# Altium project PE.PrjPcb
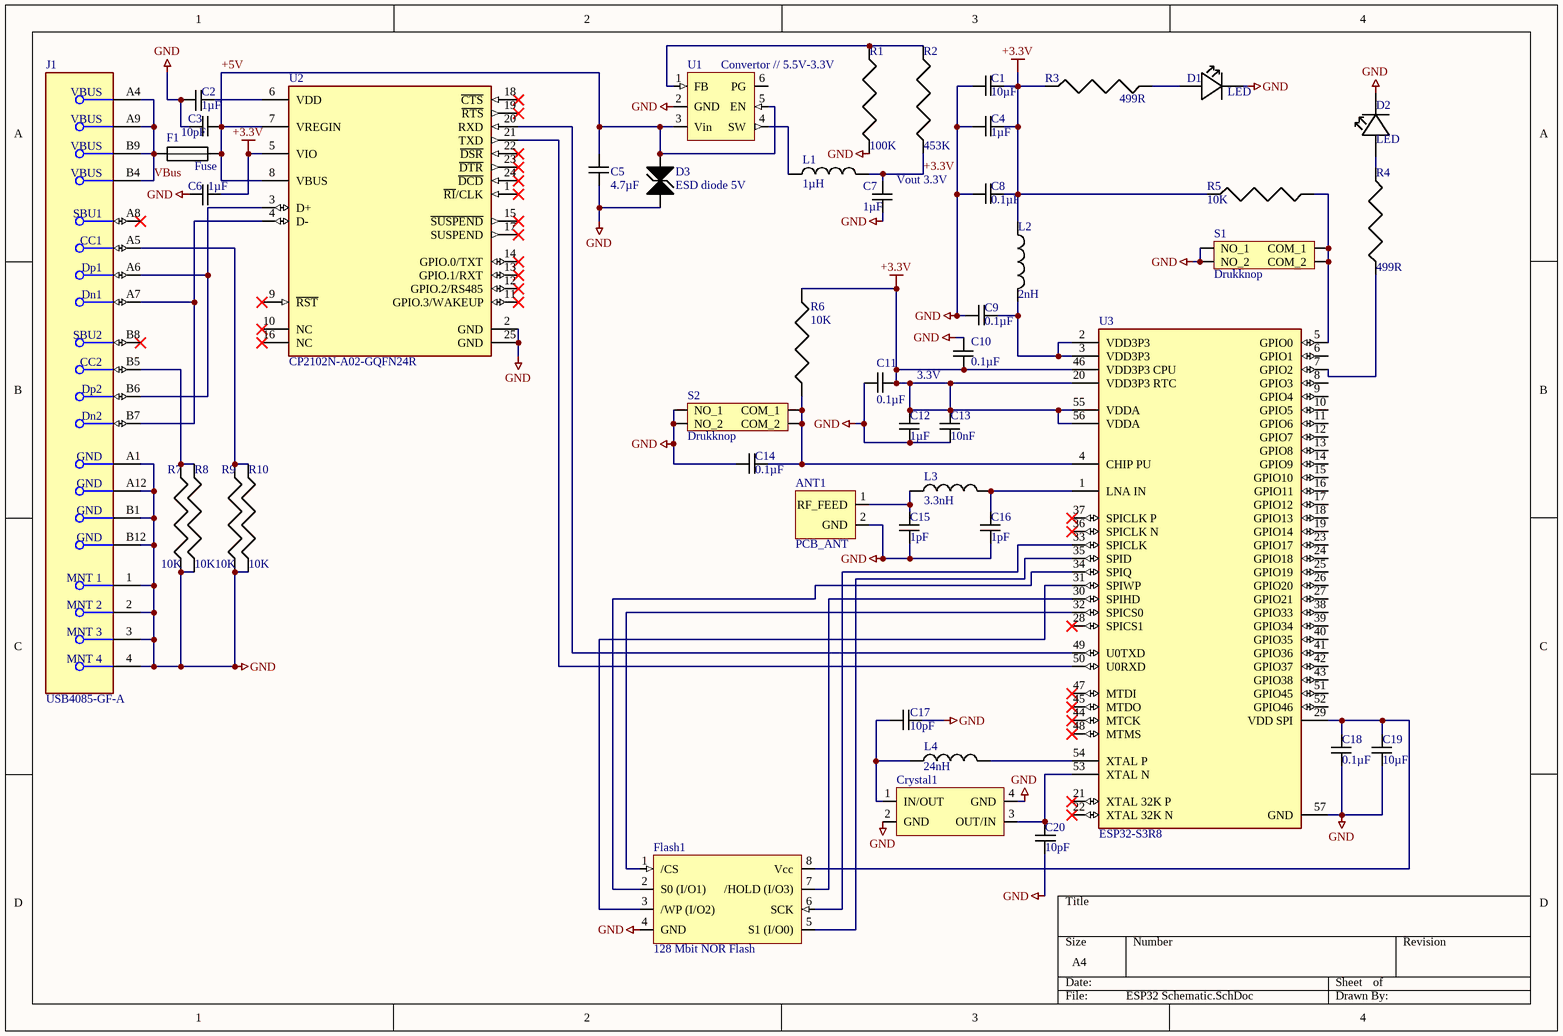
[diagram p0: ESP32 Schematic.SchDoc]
1 sheet, 47 parts. Net scope: global (net labels, ports and power ports of the same name join across sheets).
Board files: PCB-v1.PcbDoc, PCB-v2.PcbDoc, PCB-v3.PcbDoc

## Sheet ESP32 Schematic.SchDoc
size A4; SheetNumber: 1; SheetTotal: 1

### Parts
ANT1  PCB_ANT  [Antenne // RFANT5220110A0T]
C1  10µF  [CAP_General_0603]
C2  1µF  [CAP_General_0603]
C3  10pF  [CAP_General_0603]
C4  1µF  [CAP_General_0603]
C5  4.7µF  [CAP_General_0603]
C6  1µF  [CAP_General_0603]
C7  1µF  [CAP_General_0603]
C8  0.1µF  [CAP_General_0603]
C9  0.1µF  [CAP_General_0603]
C10  0.1µF  [CAP_General_0603]
C11  0.1µF  [CAP_General_0603]
C12  1µF  [CAP_General_0603]
C13  10nF  [CAP_General_0603]
C14  0.1µF  [CAP_General_0603]
C15  1pF  [CAP_General_0603]
C16  1pF  [CAP_General_0603]
C17  10pF  [CAP_General_0603]
C18  0.1µF  [CAP_General_0603]
C19  10µF  [CAP_General_0603]
C20  10pF  [CAP_General_0603]
Crystal1  Crystal  [Crystal // ECS­400­8­47B2­CKM­TR]  (value not drawn)
D1  LED  [LED // KRDELPS1.22-UIVG-46-H3Q4-XX]
D2  LED  [LED // KRDELPS1.22-UIVG-46-H3Q4-XX]
D3  ESD diode 5V  [ESD diode 5V // SMF5.0A]
F1  Fuse  [Fuse // 0603L050SLYR]
Flash1  128 Mbit NOR Flash  [128 Mbit NOR Flash // AT25QF128A-MHB-T]
J1  USB4085-GF-A  [USB-C connector // USB4085-GF-A]
L1  1µH  [Inductor 1µH // MLP2520H1R0MT0S1]
L2  2nH  [Inductor 2nH // MLG1005S2N0BTD25]
L3  3.3nH  [Inductor 3.3nH // AIMC-0805-3N3]
L4  24nH  [Inductor 24 nH // 36501J24NJTDG]
R1  100K  [RES_100K_0603]
R2  453K  [RES_453K_0603]
R3  499R  [RES_499R_0603]
R4  499R  [RES_499R_0603]
R5  10K  [RES_10K_0603_1]
R6  10K  [RES_10K_0603_1]
R7  10K  [RES_10K_0603_1]
R8  10K  [RES_10K_0603_1]
R9  10K  [RES_10K_0603_1]
R10  10K  [RES_10K_0603_1]
S1  Drukknop  [Tactile Switches // FSM4JSMAATR]
S2  Drukknop  [Tactile Switches // FSM4JSMAATR]
U1  Convertor // 5.5V-3.3V  [CONVERTOR // TLV62569APDRLR]
U2  CP2102N-A02-GQFN24R  [USB Bridge // CP2102N-A02-GQFN24R]
U3  ESP32-S3R8  [FP-ESP32-S3R8]

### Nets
+3.3V: C1.2 C4.2 C6.1 C7.2 C8.2 C10.1 C11.2 C12.2 C13.2 L1.2 L2.1 R2.2 R3.1 R5.1 R6.2 U2.5(VIO) U3.20(VDD3P3_RTC) U3.46(VDD3P3_CPU) U3.55(VDDA) U3.56(VDDA)
GND: ANT1.2(GND) C1.1 C2.2 C3.1 C4.1 C5.1 C6.2 C7.1 C8.1 C9.1 C10.2 C11.1 C12.1 C13.1 C14.1 C15.1 C16.1 C17.2 C18.1 C19.1 C20.2 Crystal1.2(GND) Crystal1.4(GND) D1.2 D2.2 D3.2 Flash1.4(GND) J1.1(MNT_1) J1.2(MNT_2) J1.3(MNT_3) J1.4(MNT_4) J1.A1(GND) J1.A12(GND) J1.B1(GND) J1.B12(GND) R1.1 R7.1 R8.1 R9.1 R10.1 S1.3(NO_1) S1.4(NO_2) S2.3(NO_1) S2.4(NO_2) U1.2(GND) U2.2(GND) U2.25(GND) U3.57(GND)
+5V: C3.2 C5.2 D3.1 F1.2 U1.3(Vin) U1.5(EN) U2.7(VREGIN) U2.8(VBUS)
VBus: F1.1 J1.A4(VBUS) J1.A9(VBUS) J1.B4(VBUS) J1.B9(VBUS)
NetANT1_1: ANT1.1(RF_FEED) C15.2 L3.1
NetC2_1: C2.1 U2.6(VDD)
NetC9_2: C9.2 L2.2 U3.2(VDD3P3) U3.3(VDD3P3)
NetC14_2: C14.2 R6.1 S2.1(COM_1) S2.2(COM_2) U3.4(CHIP_PU)
NetC16_2: C16.2 L3.2 U3.1(LNA_IN)
NetC17_1: C17.1 Crystal1.1(IN/OUT) L4.1
NetC18_2: C18.2 C19.2 Flash1.8(Vcc) U3.29(VDD_SPI)
NetC20_1: C20.1 Crystal1.3(OUT/IN) U3.53(XTAL_N)
NetD1_1: D1.1 R3.2
NetD2_1: D2.1 R4.2
NetFlash1_1: Flash1.1(/CS) U3.32(SPICS0)
NetFlash1_2: Flash1.2(S0_(I/O1)) U3.34(SPIQ)
NetFlash1_3: Flash1.3(/WP_(I/O2)) U3.31(SPIWP)
NetFlash1_5: Flash1.5(S1_(I/O0)) U3.35(SPID)
NetFlash1_6: Flash1.6(SCK) U3.33(SPICLK)
NetFlash1_7: Flash1.7(/HOLD_(I/O3)) U3.30(SPIHD)
NetJ1_A5: J1.A5(CC1) R9.2 R10.2
NetJ1_A6: J1.A6(Dp1) J1.B6(Dp2) U2.3(D+)
NetJ1_A7: J1.A7(Dn1) J1.B7(Dn2) U2.4(D-)
NetJ1_B5: J1.B5(CC2) R7.2 R8.2
NetL1_1: L1.1 U1.4(SW)
NetL4_2: L4.2 U3.54(XTAL_P)
NetR1_2: R1.2 R2.1 U1.1(FB)
NetR4_1: R4.1 U3.7(GPIO2)
NetR5_2: R5.2 S1.1(COM_1) S1.2(COM_2) U3.5(GPIO0)
NetU2_20: U2.20(RXD) U3.49(U0TXD)
NetU2_21: U2.21(TXD) U3.50(U0RXD)

Not connected (* = marked no-connect by the designer): J1 A8(SBU1)* B8(SBU2)*; U1 6(PG); U2 1(~{RI}/CLK)* 9(~{RST})* 10(NC)* 11(GPIO.3/WAKEUP)* 12(GPIO.2/RS485)* 13(GPIO.1/RXT)* 14(GPIO.0/TXT)* 15(~{SUSPEND})* 16(NC)* 17(SUSPEND)* 18(~{CTS})* 19(~{RTS})* 22(~{DSR})* 23(~{DTR})* 24(~{DCD})*; U3 6(GPIO1) 8(GPIO3) 9(GPIO4) 10(GPIO5) 11(GPIO6) 12(GPIO7) 13(GPIO8) 14(GPIO9) 15(GPIO10) 16(GPIO11) 17(GPIO12) 18(GPIO13) 19(GPIO14) 21(XTAL_32K_P)* 22(XTAL_32K_N)* 23(GPIO17) 24(GPIO18) 25(GPIO19) 26(GPIO20) 27(GPIO21) 28(SPICS1)* 36(SPICLK_N)* 37(SPICLK_P)* 38(GPIO33) 39(GPIO34) 40(GPIO35) 41(GPIO36) 42(GPIO37) 43(GPIO38) 44(MTCK)* 45(MTDO)* 47(MTDI)* 48(MTMS)* 51(GPIO45) 52(GPIO46)

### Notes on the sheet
- (near C7) Vout 3.3V
- 3.3V

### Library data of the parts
ANT1 = Antenne // RFANT5220110A0T
C1-C20 = CAP_General_0603: Capacitor SMD 0603 ?pF
Crystal1 = Crystal // ECS­400­8­47B2­CKM­TR
D1 D2 = LED // KRDELPS1.22-UIVG-46-H3Q4-XX
D3 = ESD diode 5V // SMF5.0A
F1 = Fuse // 0603L050SLYR
Flash1 = 128 Mbit NOR Flash // AT25QF128A-MHB-T
J1 = USB-C connector // USB4085-GF-A: CONN RCPT USB2.0 TYPE C 24POS RA; Gender: Receptacle; Number of Positions: 16
L1 = Inductor 1µH // MLP2520H1R0MT0S1
L2 = Inductor 2nH // MLG1005S2N0BTD25
L3 = Inductor 3.3nH // AIMC-0805-3N3
L4 = Inductor 24 nH // 36501J24NJTDG
R1 = RES_100K_0603: Resistor SMD 0603 100K
R2 = RES_453K_0603: Resistor SMD 0603 453K
R3 R4 = RES_499R_0603: Resistor SMD 0603 499R
R5-R10 = RES_10K_0603_1: Resistor SMD 0603 10K
S1 S2 = Tactile Switches // FSM4JSMAATR
U1 = Convertor // TLV62569APDRLR
U2 = USB Bridge // CP2102N-A02-GQFN24R: IC USB TO UART BRIDGE QFN24; Manufacturer Lifecycle Status: FULL PRODUCTION; NexarPartId: 99772192; Max Junction Temperature (Tj): 105°C; Min Supply Voltage: 1.71V; Max Supply Voltage: 3.6V; Number of Digital IO: 4; Interface: I2C, RS-485, UART, USB
U3 = ESP32-S3: ESP32-S3R8 RF System on a Chip - SoC SMD IC, Dual-Core MCU, Wi-Fi 2.4G BLE 5.0 Combo; NexarPartId: 118292493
